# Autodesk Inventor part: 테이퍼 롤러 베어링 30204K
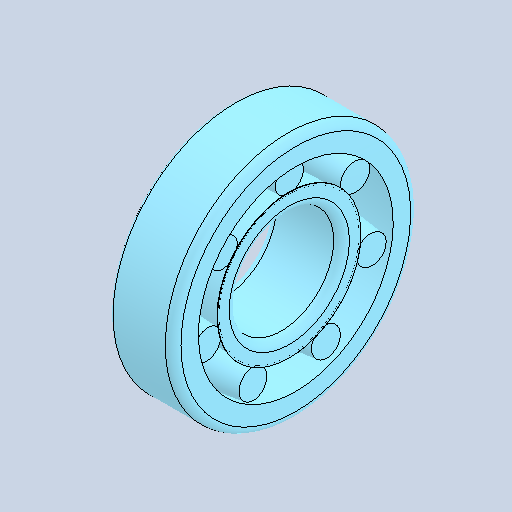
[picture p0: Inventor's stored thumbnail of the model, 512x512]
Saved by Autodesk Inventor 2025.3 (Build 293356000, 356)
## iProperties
Created: 2026-01
Part Number: 테이퍼 롤러 베어링 30204K
Material: 강철, 연강
Description: 테이퍼 롤러 베어링
Document SubType Name: Modeling
Designer: pc6
Density: 7.85 g/cm^3
Appearance: 기본값
Author: jhkim
Sending System: Autodesk Inventor 2026
Preprocessor: ST-DEVELOPER v20.1
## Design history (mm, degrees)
feature "Solid1"
feature "Solid1:1"
node "솔리드1"
node "솔리드2"
